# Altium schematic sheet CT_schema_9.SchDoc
size 274 x 160 mm
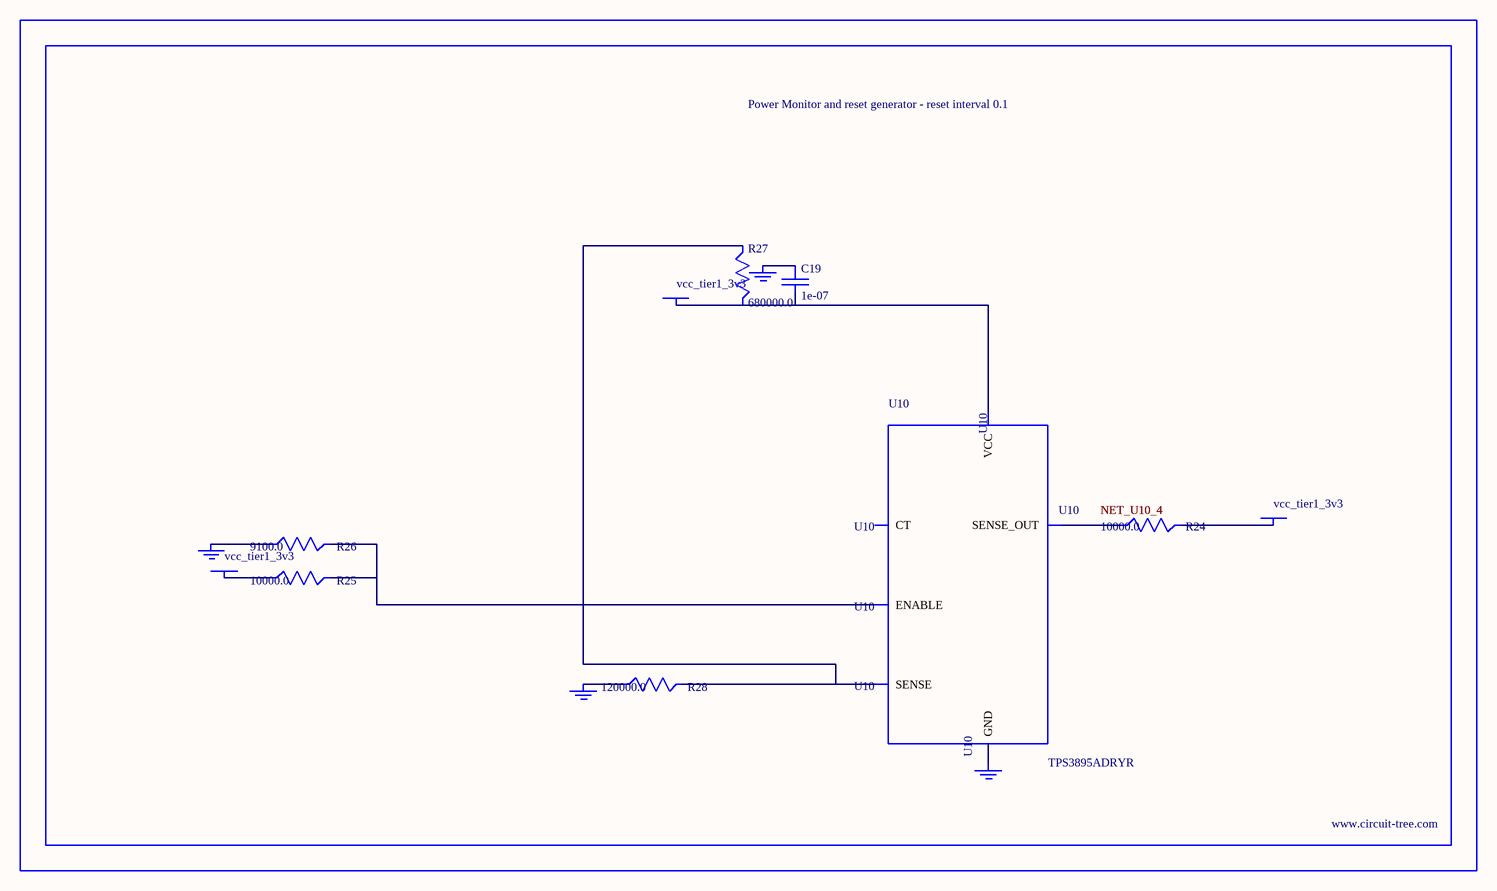
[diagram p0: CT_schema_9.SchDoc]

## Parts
BORDER8  (no value)
C19  1e-07  [C0402]
GND_INSTANCE_8_0  (no value)
GND_INSTANCE_8_1  (no value)
GND_INSTANCE_8_2  (no value)
GND_INSTANCE_8_3  (no value)
POWER_INSTANCE_8_0  vcc_tier1_3v3
POWER_INSTANCE_8_1  vcc_tier1_3v3
POWER_INSTANCE_8_2  vcc_tier1_3v3
R24  10000.0  [R0603]
R25  10000.0  [R0603]
R26  9100.0  [R0603]
R27  680000.0  [R0603]
R28  120000.0  [R0603]
U10  TPS3895ADRYR  [SON-6]

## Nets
NetC19_1: C19.1 GND_INSTANCE_8_2.0(GND)
NetC19_2: C19.2 POWER_INSTANCE_8_2.0(PWR) R27.2 U10.6(VCC)
NetGND_INSTANCE_8_0_0: GND_INSTANCE_8_0.0(GND) R26.1
NetGND_INSTANCE_8_1_0: GND_INSTANCE_8_1.0(GND) R28.1
NetGND_INSTANCE_8_3_0: GND_INSTANCE_8_3.0(GND) U10.2(GND)
NetPOWER_INSTANCE_8_0_0: POWER_INSTANCE_8_0.0(PWR) R25.1
NetPOWER_INSTANCE_8_1_0: POWER_INSTANCE_8_1.0(PWR) R24.2
NetR24_1: R24.1 U10.4(SENSE_OUT)
NetR25_2: R25.2 R26.2 U10.1(ENABLE)
NetR27_1: R27.1 R28.2 U10.3(SENSE)

Not connected (* = marked no-connect by the designer): U10 5(CT)

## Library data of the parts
BORDER8 = BORDER_PAGE8
C19 = C0402C104K3RACTU
GND_INSTANCE_8_0-GND_INSTANCE_8_3 = GND
POWER_INSTANCE_8_0-POWER_INSTANCE_8_2 = PWR
R24 R25 = RC0603JR-0710KL
R26 = RC0603JR-079K1L
R27 = RC0603JR-07680KL
R28 = RC0603JR-07120KL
